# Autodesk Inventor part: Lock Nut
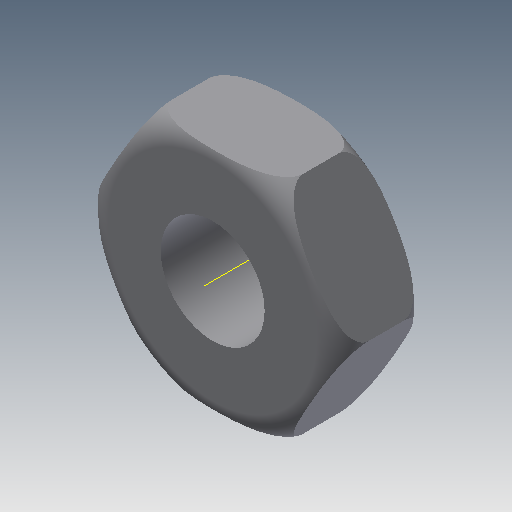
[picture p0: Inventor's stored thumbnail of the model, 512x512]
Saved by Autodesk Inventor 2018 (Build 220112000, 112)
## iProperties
Created: 2009-04
Part Number: Lock Nut
Document SubType Name: Modeling
Designer: Sham
Density: 1 g/cm^3
Material: Generic
Appearance: Default
Mass: 4.65064 g
Surface Area: 21.3319 cm^2
Volume: 4.65064 cm^3
Author: Sham
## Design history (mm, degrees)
sketch "Sketch1"
  geometry: L1 (7.5, 12.99)-(15, 0); L2 (15, 0)-(7.5, -12.99); L3 (7.5, -12.99)-(-7.5, -12.99); L4 (-7.5, -12.99)-(-15, 0); L5 (-15, 0)-(-7.5, 12.99); L6 (-7.5, 12.99)-(7.5, 12.99); C1 r 6 at (0, 0); 1 further point
  constraints: 12 end point, 1 centre point, 1 coincident, 13 other
  dimensions: "d0" = 30 distance of L1.end L4.end; "d1" = 12 diameter of C1
extrude "Extrusion1" new body sketch "Sketch1" distance "d2" = 10; taper "d3" = 0 deg
sketch "Sketch2"
  geometry: L1 (-12, 0)-(-12, -0.022); L2 (-15, 7)-(-15, 3); L3 (0, -2.87)-(0, 12.87) reference; A1 r 3 centre (-12, 7) between (-12, 10) and (-15, 7); A2 r 3 centre (-12, 3) between (-15, 3) and (-12, 0)
  constraints: 4 end point, 4 point on circle, 2 centre point, 1 tangent
revolve "Revolution1" sketch "Sketch2" stored, may be unused: angle "d7" = 90 deg
body "Solid1"
other parameters: "d6" = 90 deg
